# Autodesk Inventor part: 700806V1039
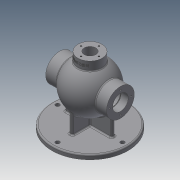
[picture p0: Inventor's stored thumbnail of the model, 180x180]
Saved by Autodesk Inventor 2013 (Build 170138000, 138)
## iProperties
Created: 2020-08
Part Number: 700806V1039
Material: Generic
Document SubType Name: Modeling
Designer: user
Density: 1 g/cm^3
Author: user
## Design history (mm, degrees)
sketch "스케치1"
  geometry: L1 (-68, 0)-(68, 0); L2 (-68, 31)-(-68, 17.5); L3 (68, 31)-(68, 17.5); L4 (-68, 31)-(-42.988, 31); L5 (42.988, 31)-(68, 31); L6 (-68, 17.5)-(-39.278, 17.5); L7 (39.278, 17.5)-(50.25, 17.5); L8 (50.25, 17.5)-(50.25, 18.5); L9 (50.25, 18.5)-(52, 18.5); L10 (52, 18.5)-(52, 17.5); L11 (52, 17.5)-(68, 17.5); A1 r 53 centre (0, 0) between (42.988, 31) and (-42.988, 31); A2 r 43 centre (0, 0) between (39.278, 17.5) and (-39.278, 17.5); 2 further points
  constraints: 22 end point, 4 perpendicular, 4 point on circle, 3 coincident, 3 parallel, 2 centre point, 2 collinear, 2 point on line, 1 horizontal, 1 midpoint
  dimensions: "d0" = 136 distance of L1.start L1.end; "d2" = 106 diameter of A1; "d6" = 62 diameter of L4 L1; "d8" = 62 diameter of L5 L1; "d9" = 86 diameter of A2; "d96" = 35 diameter of L6 L1; "d97" = 35 diameter of L11 L1; "d98" = 35 diameter of L7 L1; "d99" = 37 diameter of L9 L1; "d100" = 16 distance between parallel lines of L3 L10; "d101" = 1.75 distance between parallel lines of L10 L8
revolve "회전1" sketch "스케치1" stored, may be unused: angle "d10" = 90 deg
node "작업 평면1"
sketch "스케치2"
  geometry: C1 r 85 at (0, 0); 1 further point
  constraints: 1 centre point, 1 coincident
  dimensions: "d12" = 170 diameter of C1
extrude "돌출1" join sketch "스케치2" distance "d13" = 10; taper "d14" = 0 deg
sketch "스케치3"
  geometry: L1 (52, 4)-(-52, 4); L2 (-52, 4)-(-52, -4); L3 (-52, -4)-(52, -4); L4 (52, -4)-(52, 4); L5 (52, 4)-(-52, -4); L6 (-52, 4)-(52, -4); C1 r 85 at (0, 0) reference
  constraints: 12 end point, 2 midpoint, 2 parallel, 1 horizontal, 1 perpendicular
  dimensions: "d15" = 104 distance of L3.end L2.end; "d16" = 8 distance of L2.end L1.end
extrude "돌출2" join sketch "스케치3" stored distance "d17" = 0; taper "d18" = 0 deg
node "작업 평면2"
sketch "스케치5"
  geometry: C1 r 27 at (0, 0); 1 further point
  constraints: 1 centre point, 1 coincident
  dimensions: "d24" = 54 diameter of C1
extrude "돌출4" join sketch "스케치5" stored distance "d25" = 10; taper "d26" = 0 deg
sketch "스케치6"
  geometry: C1 r 27 at (0, 0) reference; C2 r 13 at (0, 0)
  constraints: 1 centre point, 1 coincident
  dimensions: "d27" = 26 diameter of C2
extrude "돌출5" cut sketch "스케치6" stored distance "d28" = 10; taper "d29" = 0 deg
sketch "스케치7"
  geometry: L1 (4, -43)-(-4, -43); L2 (-4, -43)-(-4, 43); L3 (-4, 43)-(4, 43); L4 (4, 43)-(4, -43); L5 (4, -43)-(-4, 43); L6 (-4, -43)-(4, 43); C1 r 85 at (0, 0) reference
  constraints: 12 end point, 2 midpoint, 2 parallel, 1 horizontal, 1 perpendicular
  dimensions: "d30" = 8 distance of L2.end L3.end; "d31" = 86 distance of L1.end L2.end
extrude "돌출6" join sketch "스케치7" stored distance "d32" = 10; taper "d33" = 0 deg
node "작업 평면3"
sketch "스케치8"
  geometry: L1 (-27, 65)-(27, 65) reference; L2 (-27, 45.607)-(27, 45.607) reference; L3 (-27, 65)-(27, 65) reference; 2 further points
  constraints: 1 other
  dimensions: "d35" = 9 distance from line of L1 point (0, 56); "d37" = 27 horizontal distance of point (0, 56) L1.start
feature "엠보싱1" sketch "스케치8" dims "d0" = 136, "d2" = 106, "d6" = 62, "d8" = 62, "d9" = 86, "d15" = 104, "d16" = 8, "d38" = 0.5, "d39" = 0, "d96" = 35, "d97" = 35, "d98" = 35, "d99" = 37, "d100" = 16, "d101" = 1.75
chamfer "모따기1" distance "d45" = 1; stored, may be unused: second distance "d46" = 2, angle "d47" = 45 deg
fillet "모깎기1" dims "d48" = 3
fillet "모깎기2" dims "d49" = 3
fillet "모깎기3" dims "d50" = 3
fillet "모깎기4" dims "d51" = 3
sketch "스케치9"
  geometry: C1 r 13 at (0, 0) reference; 1 further point
  constraints: 1 horizontal alignment
  dimensions: "d52" = 20 distance of point (20, 0) C1.centre
hole "구멍1" sketch "스케치9" at (20, 0) diameter "d53" = 3.242; stored, may be unused: countersink angle "d57" = 90 deg, drill point angle "d59" = 118 deg; dims "d54" = 12, "d55" = 4, "d56" = 2, "d58" = 15
sketch "스케치10"
  geometry: C1 r 31 at (0, 0) reference; 1 further point
  constraints: 1 vertical alignment
  dimensions: "d63" = 24 distance of point (0, 24) C1.centre
hole "구멍2" sketch "스케치10" at (0, 24) diameter "d64" = 3.242; stored, may be unused: countersink angle "d68" = 90 deg, drill point angle "d70" = 118 deg; dims "d65" = 12, "d66" = 4, "d67" = 2, "d69" = 15
sketch "스케치11"
  geometry: C1 r 31 at (0, 0) reference; 1 further point
  constraints: 1 vertical alignment
  dimensions: "d74" = 24 distance of point (0, 24) C1.centre
hole "구멍3" sketch "스케치11" at (0, 24) diameter "d75" = 3.242; stored, may be unused: countersink angle "d79" = 90 deg, drill point angle "d81" = 118 deg; dims "d76" = 12, "d77" = 4, "d78" = 2, "d80" = 15
sketch "스케치12"
  geometry: C1 r 82 at (0, 0) reference; 1 further point
  constraints: 1 vertical alignment
  dimensions: "d85" = 72.5 distance of point (0, 72.5) C1.centre
hole "구멍4" sketch "스케치12" at (0, 72.5) diameter "d86" = 9; stored, may be unused: countersink angle "d90" = 90 deg, drill point angle "d92" = 118 deg; dims "d87" = 12, "d88" = 4, "d89" = 2, "d91" = 15
node "솔리드1"
pattern_circular "원형 패턴1" dims angle "d61" = 360 deg
pattern_circular "원형 패턴2" dims angle "d72" = 360 deg
pattern_circular "원형 패턴3" dims angle "d83" = 360 deg
pattern_circular "원형 패턴4" dims angle "d94" = 360 deg
node "투영된 루프1"
other parameters: "d3" = 62, "d11" = -85, "d34" = 27
